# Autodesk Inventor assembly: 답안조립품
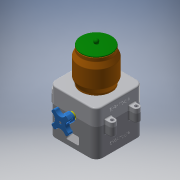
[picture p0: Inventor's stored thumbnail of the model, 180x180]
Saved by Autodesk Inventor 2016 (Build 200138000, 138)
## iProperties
Created: 2018-01
Part Number: 답안조립품
Material: 일반
Document SubType Name: Assembly
Designer: 605-15
Author: 605-15
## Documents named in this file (9)
- C:\Users\605-15\Desktop\480107V1015\답안조립품.iam
- C:\Users\605-15\Desktop\480107V1015\본체.ipt
- C:\Users\605-15\Desktop\480107V1015\본체커버.ipt
- C:\Users\605-15\Desktop\480107V1015\용기.ipt
- C:\Users\605-15\Desktop\480107V1015\용기캡.ipt
- C:\Users\605-15\Desktop\480107V1015\핸들축.ipt
- C:\Users\605-15\Desktop\480107V1015\핸들.ipt
- C:\Users\605-15\Desktop\480107V1015\볼트 M3x12.ipt
- C:\Users\605-15\Desktop\480107V1015\볼트 M4x12.ipt
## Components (2 placed, 2 different names)
1. 핸들축:1 — 각도:1
2. 핸들:1 — 각도:2
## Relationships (2: Angle 2)
- 각도:1 [Angle]: 핸들축:1
- 각도:2 [Angle]: 핸들:1
